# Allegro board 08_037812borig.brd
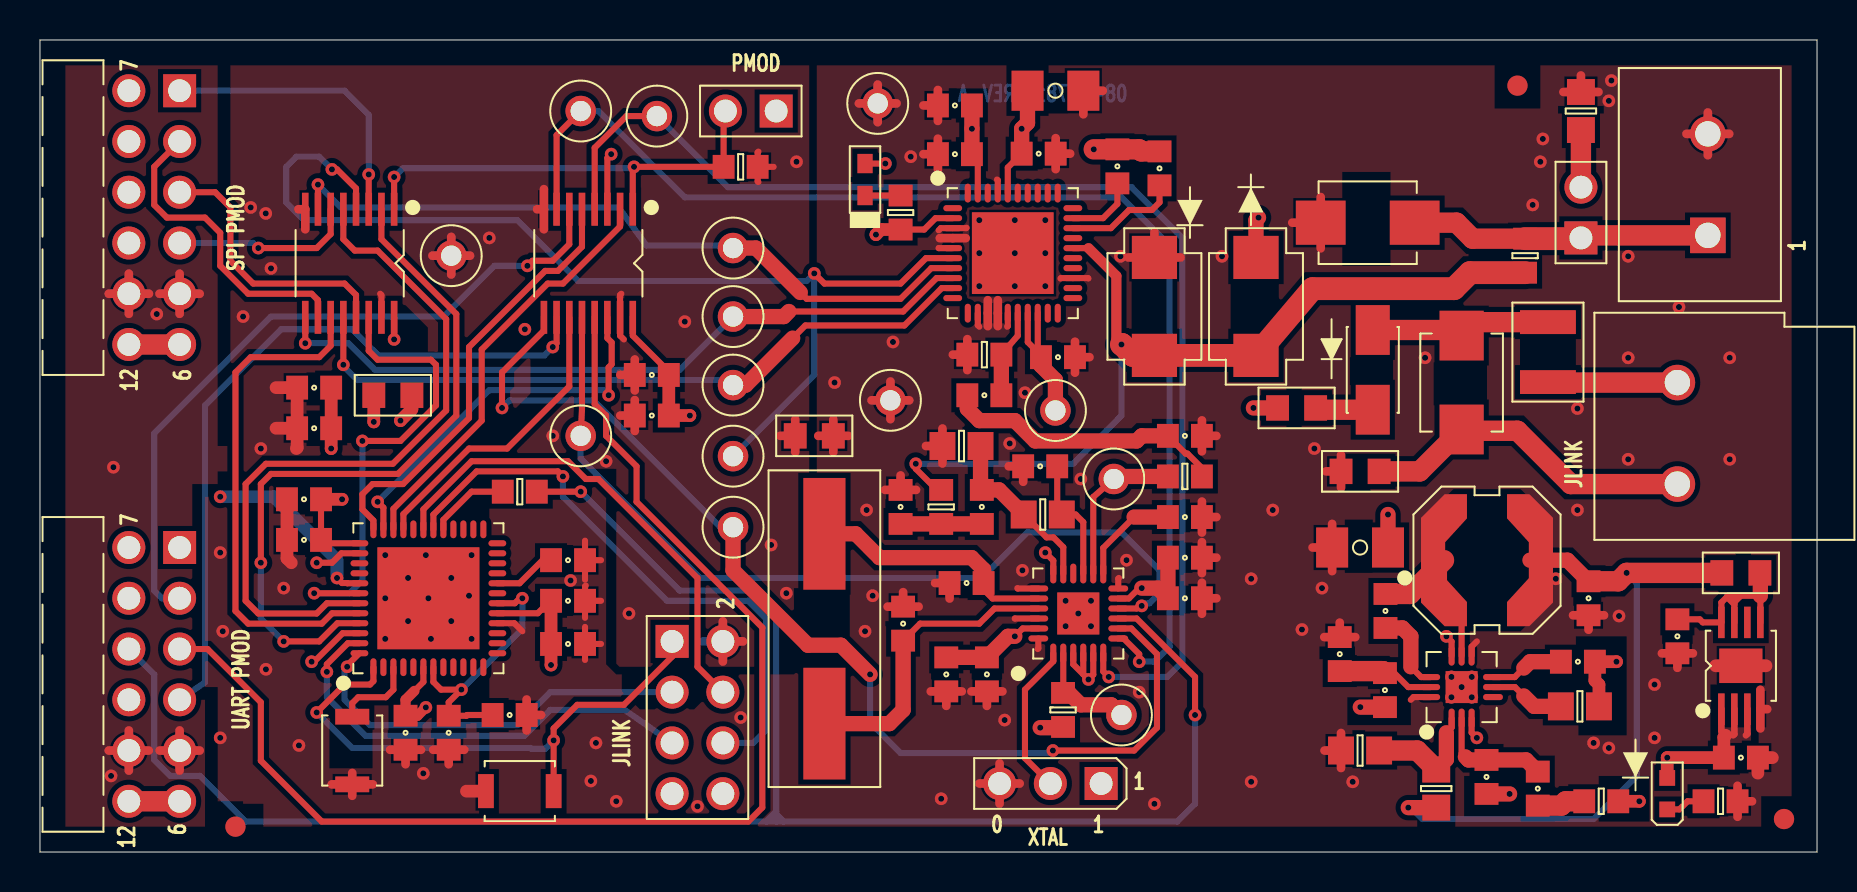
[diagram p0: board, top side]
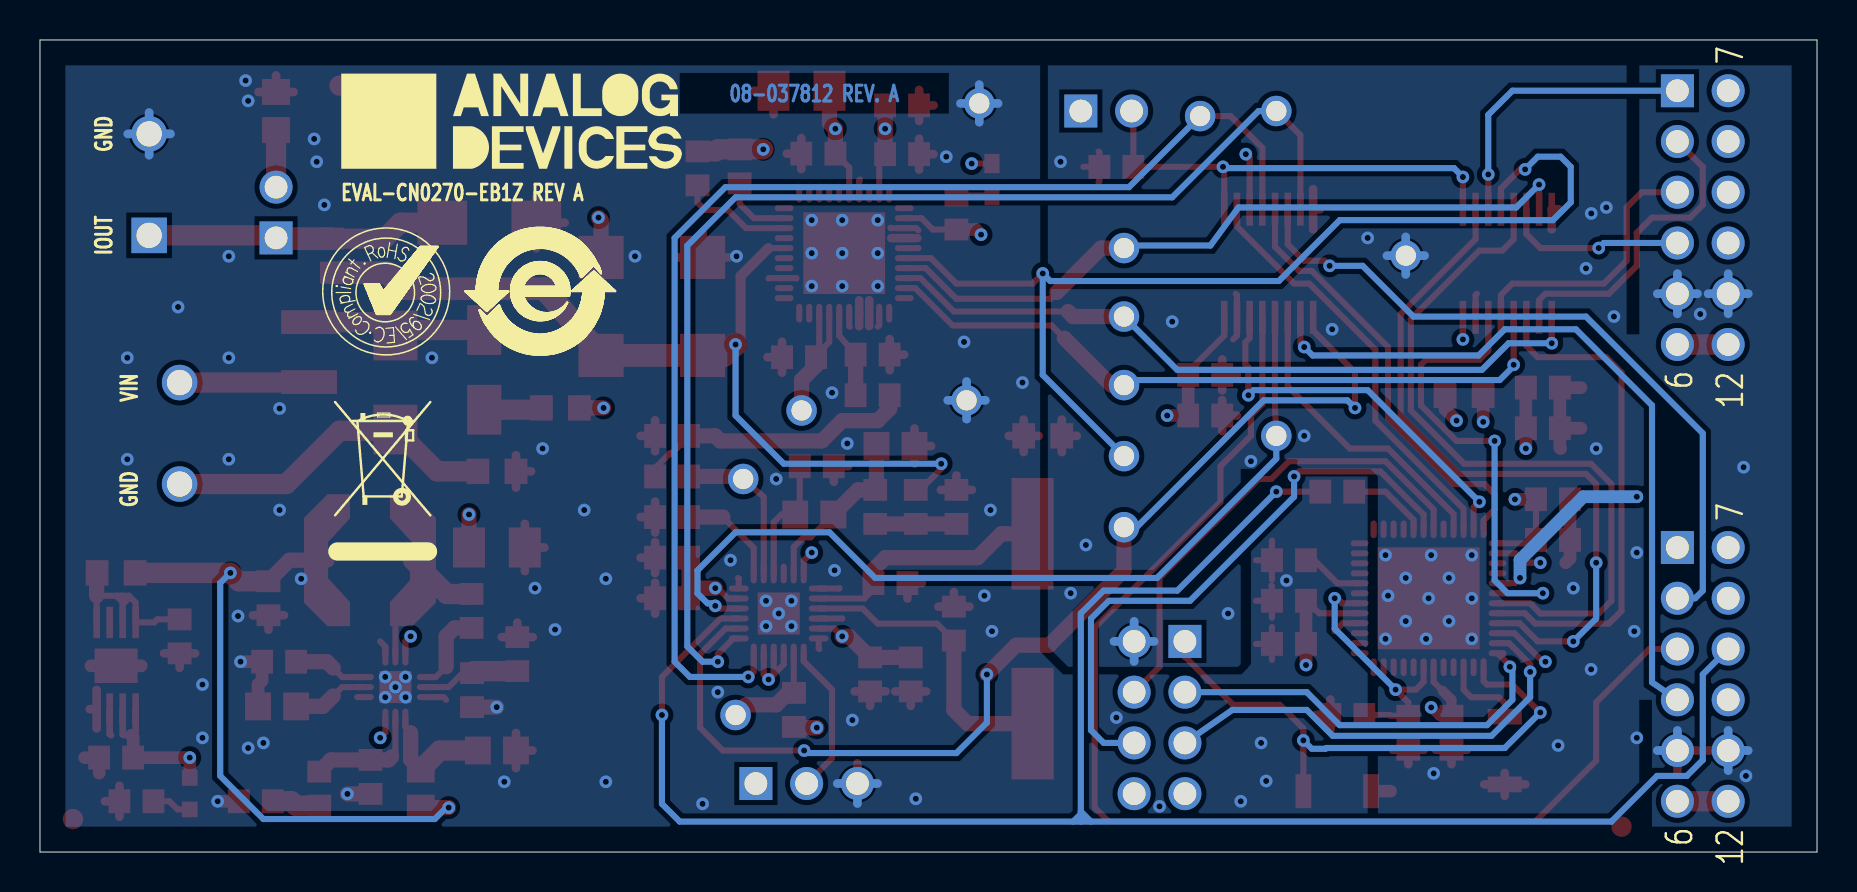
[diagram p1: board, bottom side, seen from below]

Outline 88.9 x 40.64 mm; copper layers: TOP, L2_GND, L3_PWR, BOTTOM. Coordinates in mm from the lower left corner of the outline.
Outline path: 0,40.64 0,0 88.9,0 88.9,40.64 0,40.64

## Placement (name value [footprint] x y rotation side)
C1  4700PF  [C0603]  56.01 34.21 270 top
C2  22NF  [C0603]  53.9 34.32 270 top
C3  36pF  [C0603]  43.18 11.43 90 top
C4  1uF  [C0603]  50.04 19.3 180 top
C5  36pF  [C0603]  46.35 13.46 180 top
C6  1uF  [C0603]  57.28 16.76 0 top
C7  300pF  [C0603]  47.12 17.27 270 top
C8  150PF  [C0603]  43.05 17.27 90 top
C9  0.1uF  [C0603]  57.28 14.73 180 top
C10  10uF  [C0603]  57.28 12.7 0 top
C11  10uF  [C0603]  47.37 8.89 270 top
C12  0.1uF  [C0603]  45.34 8.89 270 top
C13  10uF  [C1206H71]  50.8 38.1 180 top
C14  0.1uF  [C0603]  49.96 34.95 180 top
C15  0.1uF  [C0603]  45.77 37.36 180 top
C16  10uF  [C0603]  45.77 34.93 0 top
C17  0.1uF  [C0603]  50.93 24.77 0 top
C18  1uF  [C1206]  66.04 15.24 180 top
C19  680pF  [C0603]  74.93 3.17 270 top
C20  6.8PF  [C0603]  72.36 3.76 270 top
C21  0.01uF  [C0603]  76.94 9.53 0 top
C22  0.01uF  [C0603]  67.31 12.06 90 top
C23  1uF  [C0603]  67.28 8.1 90 top
C24  1uF  [C0603]  65.02 9.91 90 top
C25  4.7uF  [C0603]  77.47 12.7 270 top
C26  4.7uF  [C0603]  85.09 4.72 0 top
C27  10uF  [C0603]  13.72 23.24 180 top
C28  0.1uF  [C0603]  13.72 21.21 180 top
C29  10uF  [C0603]  30.61 23.88 180 top
C30  0.1uF  [C0603]  30.61 21.84 180 top
C31  1uF  [C0603]  81.91 10.79 270 top
C32  0.47uF  [C0603]  26.42 14.61 180 top
C33  0.47uF  [C0603]  20.45 5.97 90 top
C34  0.47uF  [C0603]  23.49 6.86 180 top
C35  10uF  [C0603]  26.42 12.57 180 top
C36  0.1uF  [C0603]  26.42 10.41 180 top
C37  0.1uF  [C0603]  13.21 17.65 180 top
C38  10uF  [C0603]  13.21 15.62 180 top
C39  0.1uF  [C0603]  18.29 5.97 270 top
CD  5002  [CNKEY5001TP]  30.86 36.83 0 top
CH  8200PF  [C0603]  47.24 22.86 0 top
CL  4700PF  [C0603]  57.28 20.83 0 top
CLKOUT  5002  [CNKEY5001TP]  54.1 6.86 0 top
CR1  SMBJ24CA  [DO214AA-5]  66.42 31.5 180 top
CR2  SMBJ36CA  [DO214AA-5]  71.12 23.5 90 top
D1  SMBJ24A  [DO214AA4]  55.75 27.3 90 top
D2  SMBJ24A  [DO214AA4]  60.83 27.3 270 top
D3  SBR1A40SA-13  [SMA-2]  66.67 24.13 90 top
DS1  APT1608SRCPRV  [LED0603]  41.27 33.66 90 top
DS2  LNJ312G83RA (green)  [LED0603-2]  81.41 2.92 90 top
E1  330OHM  [L0805]  62.86 22.23 180 top
E2  330OHM  [L0805]  66.04 19.05 180 top
E3  330OHM  [L0805]  38.73 20.83 0 top
E4  1K OHM  [L0805]  17.65 22.86 0 top
E5  1K OHM  [L0805]  85.09 13.97 0 top
F1  0.05A  [F1210_A]  75.44 25.02 90 top
HART_O  5002  [CNKEY5001TP]  53.72 18.67 0 top
JP1  TSW-102-08-G-S  [CNSAMTEC1X2H330LD36]  36.83 37.08 180 top
JP2  SAMTECTSW10608GS3PIN  [CNBERG1X3H205LD36]  53.09 3.43 180 top
L1  12uH  [LSMSQ236H138]  72.39 14.61 0 top
LATCH  5002  [CNKEY5001TP]  34.67 19.81 0 top
NOREF  -  []  -27.56 -102.74 0 top
NOREF#2  -  []  -150.37 -245.05 0 top
NOREF#3  -  []  0 0 90 top
NOREF#4  -  [unnamed#2]  87.25 1.65 0 top
NOREF#5  -  []  0 0 0 top
NOREF#6  -  []  87.25 1.65 0 top
NOREF#7  -  [unnamed#2]  73.91 38.35 0 top
NOREF#8  -  []  -150.37 -245.05 0 top
NOREF#9  -  []  0 40.64 270 top
NOREF#10  -  []  -150.37 -245.05 0 top
NOREF#11  -  []  88.9 0 0 top
NOREF#12  -  []  0 0 0 top
NOREF#13  -  []  -48.45 134.05 0 top
NOREF#14  -  [unnamed#2]  9.78 1.27 0 top
NOREF#15  -  []  0 40.64 0 top
NOREF#16  -  []  88.9 40.64 0 top
NOREF#17  -  []  88.9 40.64 180 top
NOREF#18  -  []  87.25 1.65 0 top
NOREF#19  -  []  88.9 0 90 top
NOREF#20  -  []  41.91 69.02 0 top
NOREF#21  -  []  88.9 0 0 top
NOREF#22  -  []  71.75 19.68 180 bottom
NOREF#23  -  []  63.88 28.07 180 bottom
NOREF#24  -  []  71.63 27.94 180 bottom
NOREF#25  -  []  65.28 36.58 180 bottom
P1  TSW-106-25-F-D-RA  [CNHDRRA2X6H240]  6.98 38.1 270 top
P2  TSW-102-08-G-S  [CNSAMTEC1X2H330LD36]  77.09 30.73 90 top
P3  OSTTC022162  [CNHDR1X2H406]  83.44 30.86 90 top
P4  ED125/2DS  [CNOSTED125-2DS]  81.91 23.5 270 top
P5  TSW-106-25-F-D-RA  [CNHDRRA2X6H240]  6.98 15.24 270 top
P7  TSW-104-08-T-D  [CNSAMTEC2X4H330LD36]  31.62 10.54 270 top
R1  10K  [R0603]  35.05 34.29 0 top
R2  1.2MEG  [R0805]  50.16 16.89 180 top
R3  1.2MEG  [R0805]  46.1 20.32 180 top
R4  0  [R0603]  24 18.03 0 top
R5  150K  [R0603]  45.08 17.27 90 top
R6  0  [R0603]  51.18 7.11 270 top
R7  15K  [R0603]  47.24 24.89 180 top
R8  130  [R0603]  43.05 32 270 top
R9  18  [R0603]  74.29 29.84 90 top
R10  499  [R0805]  77.09 37.08 90 top
R11  127K  [R0805]  77.04 7.29 0 top
R12  130  [R0603]  78.1 2.54 0 top
R13  13.7K  [R0805]  66.04 5.08 180 top
R14  73.2K  [R0805]  69.85 3.17 270 top
R15  130  [R0603]  84.07 2.54 0 top
REF  5002  [CNKEY5001TP]  50.8 22.1 0 top
RH  27K  [R0603]  57.28 18.8 0 top
RTS  5002  [CNKEY5001TP]  34.67 16.26 0 top
RXD  5002  [CNKEY5001TP]  27.05 20.83 0 top
S1  B3U-1000P  [SWSML118W98H69]  24 3.05 0 top
S2  B3U-1000P  [SWSML118W98H69]  15.62 5.08 90 top
SCLK  5002  [CNKEY5001TP]  34.67 30.23 0 top
SDI  5002  [CNKEY5001TP]  34.67 26.8 0 top
SDO  5002  [CNKEY5001TP]  34.67 23.37 0 top
TP1  5001  [CNKEY5001TP]  42.54 22.61 0 top
TP2  5001  [CNKEY5001TP]  41.91 37.47 0 top
TP3  5001  [CNKEY5001TP]  20.57 29.84 0 top
TXD  5002  [CNKEY5001TP]  27.05 37.08 0 top
U1  AD5700-1BCPZ  [QFN24_4X4_PAD2_1X2_1]  51.94 11.94 0 top
U2  AD5420ACPZ  [QFN40_6X6_PAD4_1X4_1]  48.67 29.97 270 top
U3  ADP2441ACPZ  [QFN12_3X3_PAD1_6X1_6]  71.12 8.26 0 top
U4  ADP124ARHZ-3.3-R7  [MSOP8_PAD2_16X1_73]  85.09 9.32 0 top
U5  ADUCM360BCPZ128  [QFN48_7X7_PAD5_1X5_1]  19.43 12.7 0 top
U6  ADG774BRQZ  [QSOP16]  15.49 29.46 180 top
U7  ADG774BRQZ  [QSOP16]  27.43 29.46 180 top
Y1  3.6864MEGHz  [YSML450W190H160]  39.24 11.18 90 top

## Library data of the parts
C1 CL = CAP: Tolerance: 10; User Part Number: UPN; alternate symbols: (C0402H22_ALT,C0201-2,C0402_A,C0402_ALT); part number: CAP_SM-4700PF,50V,10,E000427,C0603; tolerance: 10
C2 = CAP: Tolerance: 10; User Part Number: UPN; alternate symbols: (C0402H22_ALT,C0201-2,C0402_A,C0402_ALT); part number: CAP_SM-22NF,16V,10,E000327,C0603; tolerance: 10
C3 C5 = CAP: Tolerance: 5; User Part Number: UPN; alternate symbols: (C0402H22_ALT,C0201-2,C0402_A,C0402_ALT); part number: CAP_SM-36PF,50V,5,E011673,C0603; tolerance: 5
C4 C6 C23 C24 C31 = CAP: Tolerance: 10; User Part Number: UPN; alternate symbols: (C0402H22_ALT,C0201-2,C0402_A,C0402_ALT); part number: CAP_SM-1UF,10V,10,E011783,C0603; tolerance: 10
C7 = CAP: Tolerance: 5; User Part Number: UPN; alternate symbols: (C0402H22_ALT,C0201-2,C0402_A,C0402_ALT); part number: CAP_SM-300PF,50V,5,E012930,C0603; tolerance: 5
C8 = CAP: Tolerance: 5; User Part Number: UPN; alternate symbols: (C0402H22_ALT,C0201-2,C0402_A,C0402_ALT); part number: CAP_SM-150PF,50V,5,E000416,C0603; tolerance: 5
C9 C12 C28 C30 C36 C37 C39 = CAP: Tolerance: 10; User Part Number: UPN; alternate symbols: (C0402H22_ALT,C0201-2,C0402_A,C0402_ALT); part number: CAP_SM-0.1UF,16V,10,E015036,C0603; tolerance: 10
C10 C11 C16 C27 C29 C35 C38 = CAP: Tolerance: 20; User Part Number: UPN; alternate symbols: (C0402H22_ALT,C0201-2,C0402_A,C0402_ALT); part number: CAP_SM-10UF,10V,20,E018646,C0603; tolerance: 20
C13 = CAP: Tolerance: 10; User Part Number: UPN; alternate symbols: (C0402H22_ALT,C0201-2,C0402_A,C0402_ALT); part number: CAP_SM-10UF,50V,10,E013961,C1206H71; tolerance: 10
C14 C15 C17 = CAP: Tolerance: 10; User Part Number: UPN; alternate symbols: (C0402H22_ALT,C0201-2,C0402_A,C0402_ALT); part number: CAP_SM-0.1UF,50V,10,E011865,C0603; tolerance: 10
C18 = CAP: Tolerance: 10; User Part Number: UPN; alternate symbols: (C0402H22_ALT,C0201-2,C0402_A,C0402_ALT); part number: CAP_SM-1UF,50V,10,E011257,C1206; tolerance: 10
C19 = CAP: Tolerance: 5; User Part Number: UPN; alternate symbols: (C0402H22_ALT,C0201-2,C0402_A,C0402_ALT); part number: CAP_SM-680PF,50V,5,E010191,C0603; tolerance: 5
C20 = CAP: Tolerance: 5; User Part Number: UPN; alternate symbols: (C0402H22_ALT,C0201-2,C0402_A,C0402_ALT); part number: CAP_SM-6.8PF,50V,5,E000408,C0603; tolerance: 5
C21 C22 = CAP: Tolerance: 5; User Part Number: UPN; alternate symbols: (C0402H22_ALT,C0201-2,C0402_A,C0402_ALT); part number: CAP_SM-0.01UF,25V,5,E012400,C0603; tolerance: 5
C25 C26 = CAP: Tolerance: 10; User Part Number: UPN; alternate symbols: (C0402H22_ALT,C0201-2,C0402_A,C0402_ALT); part number: CAP_SM-4.7UF,16V,10,E020112,C0603; tolerance: 10
C32-C34 = CAP: Tolerance: 10; User Part Number: UPN; alternate symbols: (C0402H22_ALT,C0201-2,C0402_A,C0402_ALT); part number: CAP_SM-0.47UF,25V,10,E010966,C0603; tolerance: 10
CD CLKOUT HART_O LATCH REF RTS RXD SCLK SDI SDO TXD = CNTP1P: User Part Number: UPN; alternate symbols: (CNBANANA_ALT); part number: CNTP1P_TH-5002,E006153,CNKEY5001TP
CH = CAP: Tolerance: 5; User Part Number: UPN; alternate symbols: (C0402H22_ALT,C0201-2,C0402_A,C0402_ALT); part number: CAP_SM-8200PF,50V,5,E000433,C0603; tolerance: 5
CR1 = DIOZNR_V2: Tolerance: 5; User Part Number: UPN; part number: DIOZNR_V2_SM-SMBJ24CA,24V,5,E019419,DO214AA-5; tolerance: 5
CR2 = DIO_V3: Tolerance: N/A; User Part Number: UPN; part number: DIO_V3_SM-SMBJ36CA,36V,N/A,E019417,DO214AA-5; tolerance: N/A
D1 D2 = DIO: User Part Number: UPN; Tolerance: 5; alternate symbols: (DO15_ALT); part number: DIO_SM-SMBJ24A,24V,5,E019418,DO214AA4; tolerance: 5
D3 = DIO: User Part Number: UPN; Tolerance: N/A; alternate symbols: (DO15_ALT); part number: DIO_SM-SBR1A40SA-13,40V,N/A,E015547,SMA-2; tolerance: N/A
DS1 = DIOLED: Tolerance: N/A; User Part Number: UPN; part number: DIOLED_SM-APT1608SRCPRV,1.85V,N/A,E018073,LED0603; tolerance: N/A
DS2 = DIOLED: Tolerance: N/A; User Part Number: UPN; part number: DIOLED_SM-LNJ312G83RA (GREEN),2.03V,N/A,E014696,LED0603-2; tolerance: N/A
E1-E3 = FERRITE: Tolerance: 25; User Part Number: UPN; part number: FERRITE_SM-330OHM,25,E018120,L0805; tolerance: 25
E4 E5 = FERRITE: Tolerance: N/A; User Part Number: UPN; part number: FERRITE_SM-1K OHM,N/A,E011583,L0805; tolerance: N/A
F1 = FSFUSE: User Part Number: UPN; part number: FSFUSE_SM-0.05A,60V,E017159,BEL FUSE INC,0ZCB0005FF2E,SCD-016141,F1210_A,N/A
JP1 P2 = CN2P: User Part Number: UPN; part number: CN2P_TH-TSW-102-08-G-S,E006296,SAMTEC,TSW-102-08-G-S,SCD-002447,CNSAMTEC1X2H330LD36
JP2 = CN3P: User Part Number: UPN; part number: CN3P_TH-SAMTECTSW10608GS3PIN,E000812,CNBERG1X3H205LD36
L1 = IND: User Part Number: UPN; Tolerance: 20; alternate symbols: (L0402-2,L0603_ALT); part number: IND_SM-12UH,20,E020136,LSMSQ236H138; tolerance: 20
P1 P5 = CN12P_V3: User Part Number: UPN; part number: CN12P_V3_TH-TSW-106-25-F-D-RA,E018495,CNHDRRA2X6H240
P3 = CN2P: User Part Number: UPN; part number: CN2P_TH-OSTTC022162,E016936,ON SHORE TECHNOLOGY INC,OSTTC022162,SCD-016004,CNHDR1X2H406
P4 = CN2P: User Part Number: UPN; part number: CN2P_TH-ED125/2DS,E020249,ON SHORE TECHNOLOGY INC,ED125/2DS,SCD-017963,CNOSTED125-2DS
P7 = CN8P_ODD_EVEN: User Part Number: UPN; part number: CN8P_ODD_EVEN_TH-TSW-104-08-T-D,E006295,CNSAMTEC2X4H330LD36
R1 = RES: Tolerance: 1; User Part Number: UPN; alternate symbols: (RRAD984L1500W75H520LD32;TO220H590_ALT;R0402_A;R0603_A); part number: RES_SM-10K,E003671,1/10W,1,PANASONIC,ERJ-3EKF1002V,SCD-001006,R0603,N/A; tolerance: 1
R2 R3 = RES: Tolerance: 1; User Part Number: UPN; alternate symbols: (RRAD984L1500W75H520LD32;TO220H590_ALT;R0402_A;R0603_A); part number: RES_SM-1.2MEG,E003658,1/8W,1,PANASONIC,ERJ-6ENF1204V,SCD-001006,R0805,N/A; tolerance: 1
R4 R6 = RES: Tolerance: 1; User Part Number: UPN; alternate symbols: (RRAD984L1500W75H520LD32;TO220H590_ALT;R0402_A;R0603_A); part number: RES_SM-0,E004207,1/16W,1,MULTICOMP,MC0603WG00000T5E-TC,SCD-003454,R0603,N/A; tolerance: 1
R5 = RES: Tolerance: 1; User Part Number: UPN; alternate symbols: (RRAD984L1500W75H520LD32;TO220H590_ALT;R0402_A;R0603_A); part number: RES_SM-150K,E003672,1/10W,1,PANASONIC,ERJ-3EKF1503V,SCD-001006,R0603,N/A; tolerance: 1
R7 = RES: Tolerance: 0.1; User Part Number: UPN; alternate symbols: (RRAD984L1500W75H520LD32;TO220H590_ALT;R0402_A;R0603_A); part number: RES_SM-15K,E019547,1/10W,0.1,YAGEO,RT0603BRB0715KL,SCD-002985,R0603,N/A; tolerance: 0.1
R8 R12 R15 = RES: Tolerance: 1; User Part Number: UPN; alternate symbols: (RRAD984L1500W75H520LD32;TO220H590_ALT;R0402_A;R0603_A); part number: RES_SM-130,E003676,1/10W,1,PANASONIC,ERJ-3EKF1300V,SCD-001006,R0603,N/A; tolerance: 1
R9 = RES: Tolerance: 1; User Part Number: UPN; alternate symbols: (RRAD984L1500W75H520LD32;TO220H590_ALT;R0402_A;R0603_A); part number: RES_SM-18,E010183,1/10W,1,PANASONIC,ERJ-3EKF18R0V,SCD-001006,R0603,N/A; tolerance: 1
R10 = RES: Tolerance: 1; User Part Number: UPN; alternate symbols: (RRAD984L1500W75H520LD32;TO220H590_ALT;R0402_A;R0603_A); part number: RES_SM-499,E003414,1/8W,1,PANASONIC,ERJ-6ENF4990V,SCD-001006,R0805,N/A; tolerance: 1
R11 = RES: Tolerance: 1; User Part Number: UPN; alternate symbols: (RRAD984L1500W75H520LD32;TO220H590_ALT;R0402_A;R0603_A); part number: RES_SM-127K,E007901,1/8W,1,PANASONIC,ERJ-6ENF1273V,SCD-001006,R0805,N/A; tolerance: 1
R13 = RES: Tolerance: 1; User Part Number: UPN; alternate symbols: (RRAD984L1500W75H520LD32;TO220H590_ALT;R0402_A;R0603_A); part number: RES_SM-13.7K,E003644,1/8W,1,PANASONIC,ERJ-6ENF1372V,SCD-001006,R0805,N/A; tolerance: 1
R14 = RES: Tolerance: 1; User Part Number: UPN; alternate symbols: (RRAD984L1500W75H520LD32;TO220H590_ALT;R0402_A;R0603_A); part number: RES_SM-73.2K,E015003,1/8W,1,PANASONIC,ERJ-6ENF7322V,SCD-001006,R0805,N/A; tolerance: 1
RH = RES: Tolerance: 1; User Part Number: UPN; alternate symbols: (RRAD984L1500W75H520LD32;TO220H590_ALT;R0402_A;R0603_A); part number: RES_SM-27K,E004226,1/16W,1,MULTICOMP,MC 0.063W 0603 1% 27K.,SCD-003454,R0603,N/A; tolerance: 1
S1 S2 = SWSPST2PIN_V2: User Part Number: UPN; part number: SWSPST2PIN_V2_SM-B3U-1000P,E016303,SWSML118W98H69
TP1-TP3 = CNTP1P: User Part Number: UPN; alternate symbols: (CNBANANA_ALT); part number: CNTP1P_TH-5001,E005347,CNKEY5001TP
U1 = AD5700: User Part Number: UPN; part number: AD5700_SM-AD5700-1BCPZ,E019439,QFN24_4X4_PAD2_1X2_1,N/A
U2 = AD54X0: User Part Number: UPN; part number: AD54X0_SM-AD5420ACPZ,E012259,QFN40_6X6_PAD4_1X4_1,N/A
U3 = ADP2441: User Part Number: UPN; part number: ADP2441_SM-ADP2441ACPZ,E017338,QFN12_3X3_PAD1_6X1_6,N/A
U4 = ADP124: User Part Number: UPN; part number: ADP124_SM-ADP124ARHZ-3.3-R7,E012626,MSOP8_PAD2_16X1_73,N/A
U5 = ADUCM36X: User Part Number: UPN; part number: ADUCM36X_SM-ADUCM360BCPZ128,E018148,QFN48_7X7_PAD5_1X5_1,N/A
U6 U7 = ADG774: User Part Number: UPN; part number: ADG774_SM-ADG774BRQZ,E020256,ADI,ADG774BRQZ,HTTP://WWMFG.ANALOG.COM/WWMFG/APPS/HLM/LSF/EDIT/7667/ASSIGNMENTID/148940,QSOP16,N/A
Y1 = XTAL: User Part Number: UPN; part number: XTAL_SM-3.6864MEGHZ,E013571,YSML450W190H160

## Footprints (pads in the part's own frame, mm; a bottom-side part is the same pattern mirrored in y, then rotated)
C0603
  rect 1.092x1.194 smd: 1(-0.851,0) 2(0.851,0)
C1206
  rect 1.6x2.007 smd: 1(-1.397,0) 2(1.397,0)
C1206H71
  rect 1.6x2.007 smd: 1(-1.397,0) 2(1.397,0)
CNBERG1X3H205LD36
  rect 1.651x1.651 hole 1.143: 1(0,0)
  round 1.651 hole 1.143: 2(2.54,0) 3(5.08,0)
CNHDR1X2H406
  rect 1.778x1.778 hole 1.27: 1(0,0)
  round 1.778 hole 1.27: 2(5.08,0)
CNHDRRA2X6H240
  rect 1.651x1.651 hole 1.143: 1(0,0)
  round 1.651 hole 1.143: 2(2.54,0) 3(5.08,0) 4(7.62,0) 5(10.16,0) 6(12.7,0) 7(0,-2.54) 8(2.54,-2.54) 9(5.08,-2.54) 10(7.62,-2.54) 11(10.16,-2.54) 12(12.7,-2.54)
CNKEY5001TP
  round 1.524 hole 1.016: 1(0,0)
CNOSTED125-2DS
  round 1.778 hole 1.27: 1(0,0) 2(5.08,0)
CNSAMTEC1X2H330LD36
  rect 1.651x1.651 hole 1.143: 1(0,0)
  round 1.651 hole 1.143: 2(2.54,0)
CNSAMTEC2X4H330LD36
  rect 1.651x1.651 hole 1.143: 1(0,0)
  round 1.651 hole 1.143: 2(0,2.54) 3(2.54,0) 4(2.54,2.54) 5(5.08,0) 6(5.08,2.54) 7(7.62,0) 8(7.62,2.54)
DO214AA4
  rect 2.159x2.261 smd: A(2.451,0) C(-2.451,0)
DO214AA-5
  rect 2.489x2.21 smd: 1(-2.35,0) 2(2.35,0)
F1210_A
  rect 1.194x2.794 smd: 1(-1.5,0) 2(1.5,0)
L0805
  rect 1.143x1.27 smd: 1(-0.953,0) 2(0.953,0)
LED0603
  rect 0.965x0.762 smd: A(0.8,0) C(-0.8,0)
LED0603-2
  rect 0.787x0.787 smd: A(0.787,0) C(-0.787,0)
LSMSQ236H138
  custom 0.575x0.575 smd: 1(-2.151,0) 2(2.151,0)
MSOP8_PAD2_16X1_73
  rect 0.33x1.575 smd: 1(-0.975,-2.171) 2(-0.325,-2.171) 3(0.325,-2.171) 4(0.975,-2.171) 5(0.975,2.171) 6(0.325,2.171) 7(-0.325,2.171) 8(-0.975,2.171)
  rect 2.159x1.727 smd: PAD(0,0)
QFN12_3X3_PAD1_6X1_6
  oval 0.305x0.991 smd: 1(-0.5,-1.57) 2(0,-1.57) 3(0.5,-1.57) 7(0.5,1.57) 8(0,1.57) 9(-0.5,1.57)
  oval 0.991x0.305 smd: 4(1.57,-0.5) 5(1.57,0) 6(1.57,0.5) 10(-1.57,0.5) 11(-1.57,0) 12(-1.57,-0.5)
  rect 1.6x1.6 smd: PAD(0,0)
QFN24_4X4_PAD2_1X2_1
  oval 0.305x0.991 smd: 1(-1.25,-2) 2(-0.75,-2) 3(-0.25,-2) 4(0.25,-2) 5(0.75,-2) 6(1.25,-2) 13(1.25,2) 14(0.75,2) 15(0.25,2) 16(-0.25,2) 17(-0.75,2) 18(-1.25,2)
  oval 0.991x0.305 smd: 7(2,-1.25) 8(2,-0.75) 9(2,-0.25) 10(2,0.25) 11(2,0.75) 12(2,1.25) 19(-2,1.25) 20(-2,0.75) 21(-2,0.25) 22(-2,-0.25) 23(-2,-0.75) 24(-2,-1.25)
  rect 2.108x2.108 smd: PAD(0,0)
QFN40_6X6_PAD4_1X4_1
  oval 0.305x0.94 smd: 1(-2.25,-3.005) 2(-1.75,-3.005) 3(-1.25,-3.005) 4(-0.75,-3.005) 5(-0.25,-3.005) 6(0.25,-3.005) 7(0.75,-3.005) 8(1.25,-3.005) 9(1.75,-3.005) 10(2.25,-3.005) 21(2.25,3.005) 22(1.75,3.005) 23(1.25,3.005) 24(0.75,3.005) 25(0.25,3.005) 26(-0.25,3.005) 27(-0.75,3.005) 28(-1.25,3.005) 29(-1.75,3.005) 30(-2.25,3.005)
  oval 0.94x0.305 smd: 11(3.005,-2.25) 12(3.005,-1.75) 13(3.005,-1.25) 14(3.005,-0.75) 15(3.005,-0.25) 16(3.005,0.25) 17(3.005,0.75) 18(3.005,1.25) 19(3.005,1.75) 20(3.005,2.25) 31(-3.005,2.25) 32(-3.005,1.75) 33(-3.005,1.25) 34(-3.005,0.75) 35(-3.005,0.25) 36(-3.005,-0.25) 37(-3.005,-0.75) 38(-3.005,-1.25) 39(-3.005,-1.75) 40(-3.005,-2.25)
  rect 4.089x4.089 smd: PAD(0,0)
QFN48_7X7_PAD5_1X5_1
  oval 0.305x0.889 smd: 1(-2.75,-3.45) 2(-2.25,-3.45) 3(-1.75,-3.45) 4(-1.25,-3.45) 5(-0.75,-3.45) 6(-0.25,-3.45) 7(0.25,-3.45) 8(0.75,-3.45) 9(1.25,-3.45) 10(1.75,-3.45) 11(2.25,-3.45) 12(2.75,-3.45) 25(2.75,3.45) 26(2.25,3.45) 27(1.75,3.45) 28(1.25,3.45) 29(0.75,3.45) 30(0.25,3.45) 31(-0.25,3.45) 32(-0.75,3.45) 33(-1.25,3.45) 34(-1.75,3.45) 35(-2.25,3.45) 36(-2.75,3.45)
  oval 0.889x0.305 smd: 13(3.45,-2.75) 14(3.45,-2.25) 15(3.45,-1.75) 16(3.45,-1.25) 17(3.45,-0.75) 18(3.45,-0.25) 19(3.45,0.25) 20(3.45,0.75) 21(3.45,1.25) 22(3.45,1.75) 23(3.45,2.25) 24(3.45,2.75) 37(-3.45,2.75) 38(-3.45,2.25) 39(-3.45,1.75) 40(-3.45,1.25) 41(-3.45,0.75) 42(-3.45,0.25) 43(-3.45,-0.25) 44(-3.45,-0.75) 45(-3.45,-1.25) 46(-3.45,-1.75) 47(-3.45,-2.25) 48(-3.45,-2.75)
  rect 5.105x5.105 smd: PAD(0,0)
QSOP16
  rect 0.33x1.651 smd: 1(-2.223,-2.705) 2(-1.587,-2.705) 3(-0.953,-2.705) 4(-0.318,-2.705) 5(0.318,-2.705) 6(0.953,-2.705) 7(1.587,-2.705) 8(2.223,-2.705) 9(2.223,2.705) 10(1.587,2.705) 11(0.953,2.705) 12(0.318,2.705) 13(-0.318,2.705) 14(-0.953,2.705) 15(-1.587,2.705) 16(-2.223,2.705)
R0603
  rect 1.092x1.194 smd: 1(-0.851,0) 2(0.851,0)
R0805
  rect 1.295x1.397 smd: 1(-0.953,0) 2(0.953,0)
SMA-2
  rect 2.489x1.702 smd: A(1.995,0) C(-1.995,0)
SWSML118W98H69
  rect 0.787x1.702 smd: 1(-1.694,0) 2(1.694,0)
unnamed#2
  round 1.016 smd: (0,0)
YSML450W190H160
  rect 5.588x2.108 smd: 1(-4.75,0) 2(4.75,0)

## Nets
+3.3V: C9.2(N2) C10.1(N1) C11.1(N1) C12.1(N1) C15.1(N1) C16.2(N2) C26.1(N1) C37.1(N1) C38.1(N1) C39.1(N1) DS1.A(P) DS2.A(P) E4.2(N2) JP1.1(N1) JP2.1(N1) P7.8(N8) U1.3(CLK_CFG0) U1.4(CLK_CFG1) U1.5(RESET_N) U1.11(IOVCC) U1.18(VCC) U1.23(REF_EN) U2.39(DVCC) U4.1(VOUT1) U4.2(VOUT2) U4.3(VOUT_SENSE) U5.6(IOVDD1) U5.37(IOVDD2)
AGND: C3.2(N2) C4.2(N2) C5.2(N2) C6.2(N2) C8.2(N2) C9.1(N1) C10.2(N2) C11.2(N2) C12.2(N2) C13.1(N1) C14.1(N1) C15.2(N2) C16.1(N1) C17.2(N2) C18.2(N2) C20.2(N2) C21.2(N2) C23.1(N1) C24.2(N2) C25.2(N2) C26.2(N2) C31.2(N2) C32.1(N1) C34.1(N1) C35.1(N1) C36.1(N1) CL.2(N2) CR1.2(N2) D1.A(P) E2.2(N2) E3.2(N2) JP2.3(N3) P3.2(N2) R3.2(N2) R7.2(N2) R10.2(N2) R11.2(N2) R12.2(N2) R13.2(N2) R15.2(N2) TP1.1(N1) TP2.1(N1) U1.12(DGND1) U1.19(AGND) U1.22(DGND2) U1.24(FILTER_SEL) U1.PAD(EP) U2.3(GND1) U2.4(GND2) U2.5(CLEAR) U2.12(GND6) U2.13(GND7) U2.14(GND3) U2.15(GND4) U2.23(DVCC_SELECT) U2.37(GND5) U2.PAD U3.7(PGND) U3.12(AGND) U3.PAD U4.4(GND) U4.PAD(EP) U5.16(AGND)
AVDD: C1.1(N1) C2.1(N1) C13.2(N2) C14.2(N2) C18.1(N1) D2.C(N) E1.2(N2) U2.36(AVDD) U3.3(EN) U3.9(VIN)
AVDD_ADUC: C35.2(N2) C36.2(N2) E4.1(N1) U5.17(AVDD)
DGND: C27.2(N2) C28.2(N2) C29.2(N2) C30.2(N2) C33.1(N1) C37.2(N2) C38.2(N2) C39.2(N2) E3.1(N1) P1.5(GND1) P1.11(GND2) P5.5(GND1) P5.11(GND2) P7.2(N2) R1.2(N2) S1.1(A) S2.1(A) TP3.1(N1) U5.PAD U6.8(GND) U6.15(EN_N) U7.8(GND) U7.15(EN_N)
ADUC_CD: U5.34(P0.5/CTS/IRQ1) U7.2(S1A)
ADUC_LATCH: U5.45(P1.7/IRQ7/PWM5/CS0_N) U6.2(S1A)
ADUC_RTS: U5.33(P0.4/RTS/ECLKO) U7.11(S3A)
ADUC_RXD: U5.35(P0.6/IRQ2/SIN) U7.14(S4A)
ADUC_SCLK: U5.43(P1.5/IRQ5/PWM3/SCLK0) U6.5(S2A)
ADUC_SDI: U5.44(P1.6/IRQ6/PWM4/MOSI0) U6.11(S3A)
ADUC_SDO: U5.42(P1.4/PWM2/MISO0) U6.14(S4A)
ADUC_TXD: U5.36(P0.7/POR/SOUT) U7.5(S2A)
DACREF: C17.1(N1) REF.1(N1) U2.17(REFOUT) U2.18(REFIN)
DUPLEX: P5.9(P9) R4.2(N2) U1.9(DUPLEX)
FAULT: P1.9(P9) R8.2(N2) U2.2(FAULT_N) U5.41(P1.3/PWM1/DSR)
HART_CD: CD.1(N1) U1.6(CD) U7.4(D1)
HART_CLK: P5.10(P10) R6.2(N2) U5.38(P1.0/IRQ3/PWMSYNC/EXTCLK) U5.46(P2.0/SCL/UARTCLK)
HART_RTS: RTS.1(N1) U1.8(RTS_N) U7.9(D3)
HART_RXD: RXD.1(N1) U1.10(RXD) U7.12(D4)
HART_TXD: TXD.1(N1) U1.7(TXD) U7.7(D2)
IOVDD_ADUC: C27.1(N1) C28.1(N1) C29.1(N1) C30.1(N1) U6.16(VDD) U7.16(VDD)
LATCH: LATCH.1(N1) U2.6(LATCH) U6.4(D1)
PMOD_CD: P5.1(P1) U7.3(S1B)
PMOD_LATCH: P1.1(P1) U6.3(S1B)
PMOD_RTS: P5.4(P4) U7.10(S3B)
PMOD_RXD: P5.3(P3) U7.13(S4B)
PMOD_SCLK: P1.4(P4) U6.6(S2B)
PMOD_SDI: P1.2(P2) U6.10(S3B)
PMOD_SDO: P1.3(P3) U6.13(S4B)
PMOD_TXD: P5.2(P2) U7.6(S2B)
RESET: P7.1(N1) S1.2(B) U5.1(RESET_N)
RXD: P7.6(N6) U5.30(P0.1/SCLK1/SCL/SIN)
SCLK: SCLK.1(N1) U2.7(SCLK) U6.7(D2)
SDI: SDI.1(N1) U2.8(SDIN) U6.9(D3)
SDO: SDO.1(N1) U2.9(SDO) U6.12(D4)
SWCLK: P7.5(N5) U5.47(SWCLK)
SWDIO: P7.3(N3) U5.48(SWDIO)
TXD: P7.4(N4) U5.31(P0.2/MOSI1/SDA/SOUT)
UNNAMED_3_AD54X0_I52_CAP1: C1.2(N2) U2.28(CAP1)
UNNAMED_3_AD54X0_I52_CAP2: C2.2(N2) U2.29(CAP2)
UNNAMED_3_AD54X0_I52_IOUT: D1.C(N) D2.A(P) R5.2(N2) R9.1(N1) U2.26(IOUT)
UNNAMED_3_AD54X0_I52_RSET: CH.2(N2) R7.1(N1) U2.16(RSET)
UNNAMED_3_AD5700_I2_ADCIP: C7.1(N1) R2.2(N2) R3.1(N1) U1.17(ADC_IP)
UNNAMED_3_AD5700_I2_CLKOUT: CLKOUT.1(N1) R6.1(N1) U1.2(CLKOUT)
UNNAMED_3_AD5700_I2_HARTOUT: HART_O.1(N1) RH.1(N1) U1.14(HART_OUT)
UNNAMED_3_AD5700_I2_REF: C4.1(N1) R2.1(N1) U1.15(REF)
UNNAMED_3_AD5700_I2_REGCAP: C6.1(N1) U1.13(REG_CAP)
UNNAMED_3_AD5700_I2_XTAL1: C3.1(N1) U1.21(XTAL1) Y1.1(N1)
UNNAMED_3_AD5700_I2_XTAL2: C5.1(N1) U1.20(XTAL2) Y1.2(N2)
UNNAMED_3_AD5700_I2_XTALENN: JP2.2(N2) U1.1(XTAL_EN_N)
UNNAMED_3_ADG774_I113_IN: JP1.2(N2) R1.1(N1) U6.1(IN) U7.1(IN)
UNNAMED_3_CAP_I25_N2: C7.2(N2) C8.1(N1) R5.1(N1)
UNNAMED_3_CAP_I30_N1: CH.1(N1) CL.1(N1) RH.2(N2)
UNNAMED_3_CN2P_I50_N1: CR1.1(N1) P2.1(N1) P3.1(N1) R9.2(N2)
UNNAMED_3_CN2P_I77_N2: P2.2(N2) R10.1(N1)
UNNAMED_3_DIOLED_I83_N: DS1.C(N) R8.1(N1)
UNNAMED_4_ADP124_I110_EN: C31.1(N1) E5.2(N2) U4.5(EN) U4.7(VIN1) U4.8(VIN2)
UNNAMED_4_ADP2441_I109_BST: C22.1(N1) U3.10(BST)
UNNAMED_4_ADP2441_I109_COMP: C19.1(N1) C20.1(N1) U3.2(COMP)
UNNAMED_4_ADP2441_I109_FB: R13.1(N1) R14.1(N1) U3.1(FB)
UNNAMED_4_ADP2441_I109_FREQ: R11.1(N1) U3.5(FREQ)
UNNAMED_4_ADP2441_I109_SS: C21.1(N1) U3.6(SS/TRK)
UNNAMED_4_ADP2441_I109_SW: C22.2(N2) L1.1(N1) U3.8(SW)
UNNAMED_4_ADP2441_I109_VCC: C23.2(N2) C24.1(N1) U3.11(VCC)
UNNAMED_4_CAP_I116_N1: C25.1(N1) E5.1(N1) L1.2(N2) R14.2(N2)
UNNAMED_4_CAP_I120_N2: C19.2(N2) R12.1(N1)
UNNAMED_4_CN2P_I112_N1: F1.1(N1) P4.1(N1)
UNNAMED_4_CN2P_I112_N2: CR2.1(N1) E2.1(N1) P4.2(N2)
UNNAMED_4_DIO_I99_N: D3.C(N) E1.1(N1)
UNNAMED_4_DIO_I99_P: CR2.2(N2) D3.A(P) F1.2(N2)
UNNAMED_4_DIOLED_I134_N: DS2.C(N) R15.1(N1)
UNNAMED_8_ADUCM36X_I1_AVDDREG: C33.2(N2) C34.2(N2) U5.7(DVDD_REG) U5.18(AVDD_REG)
UNNAMED_8_ADUCM36X_I1_INTREF: C32.2(N2) U5.20(INT_REF)
UNNAMED_8_ADUCM36X_I1_P0: R4.1(N1) U5.29(P0.0/MISO1)
UNNAMED_8_ADUCM36X_I1_P2: S2.2(B) U5.3(P2.2/BM)
UNNAMED_8_CN12PV3_I78_VCC1: P1.6(VCC1) P1.12(VCC2)
UNNAMED_8_CN12PV3_I81_VCC1: P5.6(VCC1) P5.12(VCC2)

Pads without a net: P1 7 8 10; P5 7 8; P7 7; U1 16; U2 1 10 11 19 20 21 22 24 25 27 30 31 32 33 34 35 38 40; U3 4; U4 6; U5 2 4 5 8 9 10 11 12 13 14 15 19 21 22 23 24 25 26 27 28 32 39 40

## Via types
v1: diameter 0.635, hole 0.305, TOP to BOTTOM, 175 vias

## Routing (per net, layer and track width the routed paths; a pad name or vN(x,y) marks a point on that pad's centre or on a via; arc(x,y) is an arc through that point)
+3.3V: length 49.6
  TOP w0.305: DS1.A v1(42.29,34.46) ; U5.6 19.18,8.51 18.73,8.06 ; 52.19,8.89 51.69,9.39 U1.3 ; 52.19,8.89 v1(52.45,8.64) 52.69,8.88 U1.5 ; 52.19,8.89 U1.4 ; v1(48.77,10.79) 49.16,11.19 U1.23 ; v1(50.29,14.99) 50.69,14.58 U1.18 ; C37.1 C38.1 14.23,15.45 U5.37 ; v1(55.12,13.21) 54.99,13.21 54.47,12.69 U1.11 ; U2.39 46.92,34.63 C16.2
  TOP w0.33: 84.33,5.84 84.11,6.06 U4.1 ; U4.3 85.42,5.91 85.34,5.84 ; 84.71,5.84 84.76,5.9 U4.2
  TOP w0.508: v1(19.3,7.24) 18.88,6.82 C39.1 18.29,7.62 18.73,8.06
  TOP w0.635: DS2.A v1(81.41,4.72) C26.1 84.24,5.75 84.33,5.84 ; v1(18.03,21.59) 18.61,22.16 E4.2 ; C37.1 v1(15.11,17.65)
  TOP w0.762: v1(55.12,13.21) 55.92,13.21 C10.1 C9.2 ; v1(48.77,10.79) 48.43,10.79 C11.1 C12.1 ; C16.2 v1(46.62,36.2) C15.1
  L3_PWR w0.432: JP1.1 37.83,37.08 ; JP1.1 36.83,38.09 ; JP1.1 35.83,37.08 ; JP1.1 36.83,36.08 ; JP2.1 54.09,3.43 ; JP2.1 53.09,4.43 ; JP2.1 53.09,2.43 ; 35.17,2.92 P7.8 34.16,3.92
AGND: length 153.9
  TOP w0.305: 47.88,33.66 47.92,33.62 U2.37 ; 52.45,28.7 52.43,28.72 U2.23 51.07,28.72 51.05,28.7 ; 27.27,11.26 C36.1 ; C36.1 27.27,9.61 ; C36.1 28.07,10.41 ; 71.88,10.54 71.62,10.28 U3.7 ; C32.1 28.07,14.61 ; C32.1 27.27,15.58 ; C32.1 27.27,13.63 ; 44.96,30.23 44.96,30.22 U2.5 ; U1.12 53.94,13.68 53.97,13.72 ; C35.1 28.07,12.57 ; C35.1 27.27,13.3 27.3,13.33 ; C35.1 27.27,11.72 ; 44.96,31.11 45.06,31.22 U2.3 46.33,31.22 46.35,31.24 ; 24.13,11.05 23.73,11.45 U5.16 ; U2.15 48.42,26.32 48.39,26.29 ; 46.99,26.29 46.92,26.36 U2.12 ; U1.22 48.77,11.69 48.77,11.68 ; 68.58,7.62 68.71,7.75 U3.12 ; U1.19 48.92,13.19 48.89,13.21 ; U1.24 49.94,10.19 49.91,10.16
  TOP w0.432: 24.35,6.08 C34.1 ; C34.1 25.07,6.86 ; C34.1 24.35,7.63 ; C25.2 78.25,11.85 ; C25.2 77.47,11.12 ; C25.2 76.69,11.85 ; 58.13,13.96 C9.1 ; C9.1 58.13,15.51 ; C9.1 58.85,14.73 ; C6.2 58.85,16.76 ; C6.2 58.13,15.99 ; C6.2 58.13,17.54 ; 58.13,11.92 C10.2 ; C10.2 58.85,12.7 ; C10.2 58.13,13.48 ; TP2.1 41.91,38.41 ; TP2.1 40.97,37.47 ; TP2.1 41.91,36.52 ; TP2.1 42.85,37.47 ; P3.2 83.44,37.01 ; P3.2 83.44,34.87 ; P3.2 84.51,35.94 ; P3.2 82.37,35.94 ; C18.2 64.64,16.42 ; C18.2 64.64,14.06 ; C18.2 63.66,15.24 ; C8.2 43.83,18.12 ; C8.2 43.05,18.85 ; C8.2 42.28,18.12 ; 64.34,19.05 E2.2 ; E2.2 65.09,19.86 ; E2.2 65.09,18.24 ; 48.01,3.43 48.01,4.43 ; 48.01,3.43 49.01,3.43 ; 48.01,3.43 48.01,2.43 ; 48.01,3.43 47,3.43 ; 46.31,30.72 U2.4 45.01,30.72 ; 39.69,20.01 E3.2 ; E3.2 39.69,21.64 ; E3.2 38.94,20.83 ; E3.2 40.44,20.83 ; C31.2 82.69,9.94 ; C31.2 81.14,9.94 ; C31.2 81.91,9.22 ; R7.2 46.39,25.67 ; R7.2 45.67,24.89 ; R7.2 46.39,24.12 ; 47.42,26.32 U2.13 47.42,27.62 ; C24.2 65.8,10.76 ; C24.2 64.25,10.76 ; C24.2 65.02,11.48 ; 47.37,7.31 C11.2 ; C11.2 46.6,8.04 ; C11.2 48.15,8.04 ; 44.2,37.36 C15.2 ; C15.2 44.92,38.14 ; C15.2 44.92,36.59 ; C12.2 46.11,8.04 ; C12.2 45.34,7.31 ; C12.2 44.56,8.04 ; CL.2 58.85,20.83 ; CL.2 58.13,20.05 ; CL.2 58.13,21.6 ; 64.07,30.21 CR1.2 ; CR1.2 62.65,31.5 ; CR1.2 64.07,32.78 ; R15.2 84.92,3.32 ; R15.2 84.92,1.76 ; R15.2 85.65,2.54 ; 47.92,27.62 U2.14 47.92,26.32 ; D1.A 57.06,29.76 ; D1.A 54.44,29.76 ; D1.A 55.75,31.01 ; 76.21,38.04 R10.2 ; R10.2 77.09,38.86 ; R10.2 77.97,38.04 ; 44.78,13.46 C5.2 45.5,12.69 ; C17.2 51.78,25.54 ; C17.2 52.5,24.77 ; C17.2 51.78,23.99 ; C16.1 44.92,35.7 ; C16.1 44.2,34.93 ; C16.1 44.92,34.15 ; 50.81,34.18 C14.1 ; C14.1 51.54,34.95 ; C14.1 50.81,35.73 ; C3.2 43.18,13.01 ; C3.2 42.4,12.28 ; C3.2 43.96,12.28 ; 64.26,5.08 R13.2 ; R13.2 65.09,4.2 ; R13.2 65.09,5.96 ; 49.19,18.53 C4.2 48.46,19.3 ; 86.07,6.19 U4.4 ; U4.4 86.07,8.12 ; U4.4 86.41,7.15 ; R3.2 45.15,21.2 ; R3.2 45.15,19.44 ; R3.2 44.32,20.32 ; TP1.1 42.54,23.55 ; TP1.1 41.6,22.61 ; TP1.1 42.54,21.67 ; TP1.1 43.49,22.61 ; 53.18,38.1 C13.1 52.2,36.92
  TOP w0.635: 83.83,9.32 U4.PAD 86.35,9.32 ; 86.67,4.72 C26.2 85.94,3.95 ; R11.2 77.99,8.38 77.79,8.59 C21.2 v1(78.87,9.53) ; R12.2 v1(80.01,2.54)
  TOP w0.762: v1(66.05,7.25) C23.1 ; C20.2 v1(73.52,2.91)
  L2_GND w0.432: 48.01,2.43 48.01,3.43 ; 48.01,3.43 47,3.43 ; 48.01,3.43 49.01,3.43 ; 48.01,3.43 48.01,4.43 ; 42.54,21.67 TP1.1 ; TP1.1 42.54,23.55 ; TP1.1 43.49,22.61 ; TP1.1 41.6,22.61 ; TP2.1 42.85,37.47 ; TP2.1 41.91,36.52 ; TP2.1 41.91,38.41 ; TP2.1 40.97,37.47 ; P3.2 83.44,37.01 ; P3.2 82.37,35.94 ; P3.2 84.51,35.94 ; P3.2 83.44,34.87
  BOTTOM w0.432: 48.01,3.43 49.01,3.43 ; 48.01,3.43 48.01,2.43 ; 48.01,3.43 47,3.43 ; 40.97,37.47 TP2.1 ; TP2.1 41.91,38.41 ; TP2.1 42.85,37.47 ; TP2.1 41.91,36.52 ; 42.54,21.67 TP1.1 ; TP1.1 43.49,22.61 ; TP1.1 42.54,23.55 ; TP1.1 41.6,22.61 ; P3.2 83.44,37.01 ; P3.2 84.51,35.94 ; P3.2 82.37,35.94 ; P3.2 83.44,34.87
  vias: v1(26.54,13.59) v1(27.56,3.56) v1(27.81,5.46) v1(28.83,2.54) v1(32.89,2.29) v1(35.05,6.73) v1(39.75,23.5) v1(41.27,11.05) v1(41.35,17.12) v1(41.66,12.83) v1(42.67,25.53) v1(43.56,34.8) v1(45.08,2.67) v1(46.99,31.62) v1(46.99,29.97) v1(46.99,28.32) v1(48.26,6.6) v1(48.51,20.45) v1(48.77,31.62) v1(48.77,29.97) v1(48.77,28.32) v1(49.15,14.1) v1(49.28,22.99) v1(50.29,31.62) v1(50.29,29.97) v1(50.29,28.32) v1(51.31,12.57) v1(51.31,11.3) v1(51.94,11.94) v1(52.07,18.67) v1(52.58,12.57) v1(52.58,11.3) v1(54.05,29.82) v1(54.36,14.61) v1(54.99,8) v1(55.75,2.41) v1(59.13,29.82) v1(60.59,13.67) v1(60.59,3.51) v1(61.67,17.12) v1(63.13,11.13) v1(63.75,20.19) v1(64.13,13.21) v1(65.67,3.51) v1(69.29,24.74) v1(70.61,8.76) v1(70.61,7.75) v1(71.12,8.26) v1(71.63,8.76) v1(71.63,7.75) v1(74.68,32.39) v1(75.06,34.54) v1(75.18,35.69) v1(75.83,13.67) v1(76.91,22.2) v1(76.91,17.12) v1(77.72,5.46) v1(78.49,37.59) v1(78.49,5.21) v1(78.61,38.61) v1(78.99,11.81) v1(79.45,29.82) v1(79.45,24.74) v1(79.45,19.66) v1(80.77,8.38) v1(80.77,5.71) v1(81.99,27.28) v1(84.53,24.74) v1(84.53,19.66)
AVDD: length 15.9
  TOP w0.305: v1(71.88,5.71) 71.62,5.98 U3.3 ; C14.2 48.42,34.26 U2.36 ; U3.9 70.62,10.53 v1(70.36,10.79)
  TOP w0.762: v1(60.71,22.23) E1.2 ; C13.2 49.4,36.49 v1(49.11,36.2) C14.2 ; v1(60.96,31.75) 60.83,31.62 D2.C ; C18.1 v1(67.44,16.89)
  TOP w1.016: C1.1 55.09,35.06 54.99,35.17 C2.1 v1(52.72,35.17)
AVDD_ADUC: length 7.5
  TOP w0.305: U5.17 24.9,11.95 25.53,12.57 C35.2
  TOP w0.635: C35.2 C36.2 v1(25.57,9.36) ; E4.1 v1(16.7,21.53)
DGND: length 101.7
  TOP w0.305: R1.2 36.7,34.29 ; R1.2 35.9,35.01 35.94,35.05 ; R1.2 35.9,33.57 35.94,33.53 ; 29.08,27.94 29.02,27.88 U7.15 29.02,25.84 29.21,25.65 ; U6.15 17.08,27.88 17.02,27.94
  TOP w0.432: 4.44,5.08 5.45,5.08 ; 4.44,5.08 3.44,5.08 ; 4.44,5.08 4.44,6.08 ; 4.44,5.08 4.44,4.08 ; C39.2 19.06,5.12 ; C39.2 17.51,5.12 ; C39.2 18.29,4.39 ; 34.16,9.54 P7.2 ; P7.2 34.16,11.54 ; P7.2 35.17,10.54 ; P1.5 7.99,27.94 ; P1.5 6.98,28.94 ; P1.5 6.98,26.94 ; P1.5 5.98,27.94 ; TP3.1 21.51,29.84 ; TP3.1 19.63,29.84 ; TP3.1 20.57,28.9 ; TP3.1 20.57,30.79 ; 37.78,20.01 E3.1 ; E3.1 37.03,20.83 ; E3.1 37.78,21.64 ; 12.93,32.17 U6.8 13.27,31.17 ; 6.98,5.08 7.99,5.08 ; 6.98,5.08 6.98,6.08 ; 6.98,5.08 5.98,5.08 ; 6.98,5.08 6.98,4.08 ; C29.2 29.76,24.65 ; C29.2 29.76,23.1 ; C29.2 29.03,23.88 ; 15.62,2.81 S2.1 ; S2.1 14.59,3.39 ; S2.1 16.65,3.39 ; S2.1 15.62,3.96 ; 25.21,31.17 U7.8 ; U7.8 24.87,32.17 ; U7.8 25.21,33.17 ; C30.2 29.76,22.62 ; C30.2 29.03,21.84 ; C30.2 29.76,21.07 ; 19.67,5.12 C33.1 ; C33.1 21.22,5.12 ; C33.1 20.45,4.39 ; 3.44,27.94 P1.11 ; P1.11 4.44,26.94 ; P1.11 4.44,28.94 ; P1.11 5.45,27.94
  TOP w0.635: C28.2 11.81,21.21 ; C28.2 12.87,20.23 12.83,20.19 ; C28.2 C27.2 11.81,23.24 ; 12.57,14.48 12.36,14.69 C38.2 C37.2 ; S1.1 21.34,3.05
  L2_GND w0.305: 18.03,3.17 17.68,3.53
  L2_GND w0.432: 34.16,9.54 P7.2 ; P7.2 33.16,10.54 ; P7.2 34.16,11.54 ; P7.2 35.17,10.54 ; 4.44,5.08 4.44,6.08 ; 4.44,5.08 5.45,5.08 ; 4.44,5.08 4.44,4.08 ; 4.44,5.08 3.44,5.08 ; 5.98,27.94 P1.5 ; P1.5 6.98,26.94 ; P1.5 6.98,28.94 ; P1.5 7.99,27.94 ; 5.98,5.08 6.98,5.08 ; 6.98,5.08 6.98,6.08 ; 6.98,5.08 6.98,4.08 ; 6.98,5.08 7.99,5.08 ; 4.44,26.94 P1.11 ; P1.11 5.45,27.94 ; P1.11 3.44,27.94 ; P1.11 4.44,28.94 ; TP3.1 21.51,29.84 ; TP3.1 20.57,30.79 ; TP3.1 19.63,29.84 ; TP3.1 20.57,28.9
  BOTTOM w0.432: 20.57,28.9 TP3.1 ; TP3.1 19.63,29.84 ; TP3.1 21.51,29.84 ; TP3.1 20.57,30.79 ; P1.11 4.44,28.94 ; P1.11 5.45,27.94 ; P1.11 3.44,27.94 ; P1.11 4.44,26.94 ; 5.98,27.94 P1.5 ; P1.5 6.98,26.94 ; P1.5 7.99,27.94 ; P1.5 6.98,28.94 ; 4.44,5.08 4.44,6.08 ; 4.44,5.08 4.44,4.08 ; 4.44,5.08 3.44,5.08 ; 33.16,10.54 P7.2 ; P7.2 35.17,10.54 ; P7.2 34.16,11.54 ; P7.2 34.16,9.54 ; 7.99,5.08 6.98,5.08 6.98,6.08
  vias: v1(3.56,3.81) v1(3.67,19.26) v1(5.84,26.92) v1(9.02,14.99) v1(9.02,5.71) v1(9.14,11.05) v1(10.16,26.8) v1(10.54,32.26) v1(11.05,20.19) v1(11.29,31.96) v1(11.3,9.14) v1(11.56,29.21) v1(12.19,13.21) v1(12.95,5.33) v1(17.27,14.86) v1(17.27,12.7) v1(17.27,10.67) v1(18.41,13.72) v1(18.41,11.56) v1(19.18,3.94) v1(19.3,14.86) v1(19.43,12.7) v1(19.56,10.67) v1(20.57,13.72) v1(20.57,11.56) v1(21.46,12.83) v1(21.59,14.86) v1(21.59,10.67) v1(22.48,30.73) v1(24.26,26.16) v1(25.65,20.83) v1(28.32,19.56) v1(29.46,11.94) v1(32.26,26.54) v1(36.58,15.37) v1(37.34,12.95) v1(37.85,34.54)
ADUC_CD: length 21.2
  TOP w0.305: U5.34 17.68,17.17 22.1,21.59 22.1,25.15 25.4,28.45 26.16,28.45 29.02,31.31 U7.2
ADUC_LATCH: length 35.6
  TOP w0.305: U5.45 14.88,11.45 13.97,10.54 v1(12.19,10.54) ; v1(11.05,14.48) 11.05,18.41 11.56,18.92 17.91,18.92 20.83,21.84 20.83,26.92 17.08,30.67 U6.2
  BOTTOM w0.305: v1(11.05,14.48) 11.05,11.68 v1(12.19,10.54)
ADUC_RTS: length 15.2
  TOP w0.305: U7.11 26.48,23.3 23.37,20.19 21.46,20.19 18.18,16.91 U5.33
ADUC_RXD: length 19.5
  TOP w0.305: U7.14 28.38,25.72 28.6,25.5 28.6,24.41 28.45,24.26 v1(28.45,22.86) ; v1(16.89,17.53) 17.18,17.24 U5.35
  BOTTOM w0.305: v1(16.89,17.53) 22.48,23.11 28.19,23.11 v1(28.45,22.86)
ADUC_SCLK: length 36.4
  TOP w0.305: U6.5 15.18,30.67 15.75,30.1 16.89,30.1 20.32,26.67 20.32,22.1 17.65,19.43 11.3,19.43 10.29,18.41 10.29,12.57 10.92,11.94 13.84,11.94 14.36,12.45 U5.43
ADUC_SDI: length 25.4
  TOP w0.305: U5.44 14.62,11.95 14.1,11.43 10.41,11.43 9.78,12.06 9.78,24 10.54,24.77 13.97,24.77 14.54,25.34 U6.11
ADUC_SDO: length 23.7
  TOP w0.305: U5.42 13.72,12.95 v1(13.72,12.95) ; v1(16.13,20.57) 18.03,20.57 19.81,22.35 19.81,24.38 19.56,24.64 16.89,24.64 16.45,25.08 U6.14
  BOTTOM w0.305: v1(13.72,12.95) 15.48,12.95 16.13,13.6 v1(16.13,20.57)
ADUC_TXD: length 22.1
  TOP w0.305: U5.36 16.68,16.59 16.13,17.14 16.13,17.91 16.64,18.41 18.16,18.41 21.46,21.72 21.46,25.27 25.27,29.08 25.91,29.08 27.11,30.29 U7.5
DACREF: length 7.4
  TOP w0.305: U2.17 49.42,25.52 49.92,25.02 ; 49.92,25.02 50.08,24.86 C17.1 ; 49.92,25.02 U2.18
  TOP w0.762: REF.1 50.8,23.62 50.08,24.35 C17.1
DUPLEX: length 97.4
  TOP w0.305: v1(27.05,18.03) R4.2 ; v1(57.78,6.86) 57.78,8.76 54.86,11.69 U1.9
  BOTTOM w0.305: 36.83,1.91 36.83,2.03 ; 36.83,1.91 37.21,1.52 ; 36.83,1.91 36.83,1.52 ; 36.83,2.03 36.83,11.94 35.69,13.08 32,13.08 v1(27.05,18.03) ; 36.83,2.03 36.32,1.52 ; 36.32,1.52 10.29,1.52 8,3.81 6.51,3.81 5.71,4.61 5.71,8.89 P5.9 ; 36.32,1.52 36.83,1.52 ; 37.21,1.52 36.83,1.52 ; 37.21,1.52 56.9,1.52 57.78,2.41 v1(57.78,6.86)
FAULT: length 17.5
  TOP w0.305: v1(14.86,13.72) 15.11,13.46 15.37,13.46 15.38,13.45 U5.41 ; U2.2 44.8,31.72 44.23,31.15 R8.2
  TOP w0.635: v1(41.82,30.9) 42.08,31.15 R8.2
  L3_PWR w0.432: 4.44,32.02 P1.9 ; P1.9 5.45,33.02 ; P1.9 3.44,33.02 ; P1.9 4.44,34.02
  BOTTOM w0.635: v1(14.86,13.72) 14.86,14.61 11.69,17.78 v1(9.02,17.78)
HART_CD: length 62.2
  TOP w0.305: U7.4 27.75,35.24 29.34,36.83 CD.1 ; U1.6 53.19,9.04 v1(53.47,8.76)
  BOTTOM w0.305: v1(53.47,8.76) 56.39,8.76 57.15,9.53 57.15,30.73 54.61,33.27 34.42,33.27 CD.1
HART_CLK: length 9.5
  TOP w0.305: U5.46 15.14,10.95 13.72,9.53 v1(13.59,9.53) ; U5.38 15.08,14.95 14.6,14.48 v1(13.84,14.48)
  TOP w0.762: v1(50.04,6.22) 51.14,6.22 R6.2
  L3_PWR w0.432: 4.44,6.62 P5.10 ; P5.10 5.45,7.62 ; P5.10 3.44,7.62
HART_RTS: length 55
  TOP w0.305: v1(50.67,5.08) 54.74,5.08 55.88,6.22 55.88,9.91 54.6,11.19 U1.8 ; U7.9 25.21,26.1 23.11,24 v1(23.11,22.23)
  TOP w0.762: RTS.1 34.67,14.1 38.42,10.35 40.07,10.35 v1(41.53,8.89)
  BOTTOM w0.305: RTS.1 34.04,16.26 27.69,22.61 23.49,22.61 v1(23.11,22.23) ; v1(41.53,8.89) 41.53,6.48 43.05,4.95 50.55,4.95 v1(50.67,5.08)
HART_RXD: length 43.8
  TOP w0.305: RXD.1 27.11,22.16 U7.12 ; U1.10 54.86,12.19 54.99,12.32 v1(55.12,12.32)
  BOTTOM w0.305: RXD.1 27.05,19.68 33.02,13.72 47.12,13.72 49.4,16 54.1,16 56.01,14.1 56.01,12.95 55.5,12.45 55.24,12.45 v1(55.12,12.32)
HART_TXD: length 61.3
  TOP w0.305: TXD.1 25.84,35.88 U7.7 ; U1.7 54.21,10.69 54.99,9.91 v1(54.99,9.53)
  BOTTOM w0.305: v1(54.99,9.53) 55.75,9.53 56.51,10.29 56.51,30.35 54.1,32.77 32.26,32.77 27.94,37.08 TXD.1
IOVDD_ADUC: length 10.9
  TOP w0.305: C29.1 31.46,24.04 29.65,25.84 U7.16 ; v1(17.72,25.65) U6.16
  TOP w0.635: C27.1 C28.1 v1(14.57,20.19) ; v1(32.51,21.84) C30.1 C29.1
LATCH: length 53.9
  TOP w0.305: v1(14.6,34.16) 14.86,34.16 15.81,33.21 U6.4 ; U2.6 44.33,29.72 43.05,28.45 39.24,28.45 v1(38.73,28.96)
  BOTTOM w0.305: LATCH.1 38.73,23.88 v1(38.73,28.96) 38.35,28.57 26.92,28.57 23.88,31.62 13.21,31.62 12.32,32.51 12.32,34.29 12.83,34.8 13.97,34.8 v1(14.6,34.16)
PMOD_CD: length 6.9
  TOP w0.305: U7.3 28.38,34.73 v1(28.57,34.93)
  L3_PWR w0.432: 5.98,15.24 P5.1 ; P5.1 7.99,15.24 ; P5.1 6.98,14.24 ; P5.1 6.98,16.24
PMOD_LATCH: length 14.7
  TOP w0.305: U6.3 v1(16.45,33.91)
  BOTTOM w0.305: v1(16.45,33.91) 16.45,36.89 15.24,38.1 P1.1
PMOD_RTS: length 36.7
  TOP w0.305: v1(25.65,25.27) 25.84,25.46 U7.10
  BOTTOM w0.305: v1(25.65,25.27) 25.23,24.85 16.93,24.85 15.62,26.16 12.06,26.16 8.25,22.35 8.25,8.49 P5.4
PMOD_RXD: length 62.7
  TOP w0.305: P5.3 8.38,10.16 11.05,7.49 11.05,4.57 14.1,1.52 35.43,1.52 36.14,2.23 36.14,11.23 29.84,17.53 29.84,19.3 28.32,20.83 28.32,21.84 27.75,22.42 U7.13
PMOD_SCLK: length 9.2
  TOP w0.305: U6.6 14.54,30.92 13.84,30.23 v1(10.92,30.23)
  BOTTOM w0.305: v1(10.92,30.23) 10.67,30.48 P1.4
PMOD_SDI: length 15.7
  TOP w0.305: P1.2 5.71,34.29 5.71,32.39 6.35,31.75 8.25,31.75 9.02,30.99 9.02,29.34 10.41,27.94 13.59,27.94 13.91,27.62 U6.10
PMOD_SDO: length 13.6
  TOP w0.305: P1.3 8.76,33.02 9.52,32.26 9.52,29.59 10.67,28.45 15.24,28.45 15.81,27.88 U6.13
PMOD_TXD: length 35.7
  TOP w0.305: U7.6 26.48,30.42 25.65,29.59 24.64,29.59 v1(24.38,29.34)
  BOTTOM w0.305: v1(24.38,29.34) 22.73,29.34 20.19,26.8 11.56,26.8 5.71,20.95 5.71,13.08 6.1,12.7 P5.2
RESET: length 28.3
  TOP w0.305: S1.2 v1(25.7,5.59) 25.7,6.18 26.88,7.37 29.21,7.37 31.62,9.78 P7.1 ; U5.1 16.68,8.55 16.51,8.38 15.24,8.38 v1(13.84,6.98)
  BOTTOM w0.305: v1(13.84,6.98) 15.62,5.21 24.55,5.21 24.59,5.17 25.27,5.17 v1(25.7,5.59)
RXD: length 29.9
  TOP w0.305: v1(26.16,18.8) 25.91,19.05 21.84,19.05 19.68,16.89 U5.30
  BOTTOM w0.305: P7.6 35.69,5.46 36.32,6.1 36.32,11.68 35.43,12.57 31.37,12.57 26.16,17.78 v1(26.16,18.8)
SCLK: length 36.2
  TOP w0.305: U6.7 v1(13.91,33.4) ; U2.7 44.59,29.22 43.05,27.69 38.35,27.69 38.04,28
  TOP w0.762: SCLK.1 35.81,30.23 38.04,28
  BOTTOM w0.305: SCLK.1 34.54,30.35 30.34,30.35 28.95,32.26 15.05,32.26 v1(13.91,33.4)
SDI: length 36.1
  TOP w0.305: U6.9 v1(13.27,25.46) ; U2.8 44.85,28.72 43.18,27.05 37.46,27.05
  TOP w0.762: SDI.1 37.21,26.8 37.46,27.05
  BOTTOM w0.305: SDI.1 32,24.13 16.76,24.13 15.43,25.46 v1(13.27,25.46)
SDO: length 35.3
  TOP w0.305: U2.9 45.11,28.22 43.24,26.35 38.29,26.35 37.66,25.72 ; U6.12 v1(15.18,24.38)
  TOP w0.762: SDO.1 35.31,23.37 37.66,25.72
  BOTTOM w0.305: SDO.1 34.42,23.62 15.88,23.62 15.18,24.32 v1(15.18,24.38)
SWCLK: length 22.8
  TOP w0.305: U5.47 15.4,10.45 14.35,9.4 v1(14.35,9.02)
  BOTTOM w0.305: v1(14.35,9.02) 14.35,7.75 16.28,5.82 24.23,5.82 25.53,7.11 29.25,7.11 P7.5
SWDIO: length 20.2
  TOP w0.305: v1(15.37,9.27) 15.37,9.34 U5.48
  BOTTOM w0.305: P7.3 25.53,8 23.88,6.35 16.51,6.35 15.24,7.62 15.24,9.14 v1(15.37,9.27)
TXD: length 24.4
  TOP w0.305: P7.4 32.89,9.27 32.89,13.72 27.94,18.67 27.3,18.67 26.42,19.56 21.59,19.56 19.18,17.15 U5.31
UNNAMED_3_AD54X0_I52_CAP1: length 5.7
  TOP w0.305: U2.28 53.57,31.22 54.48,32.13 55.63,32.13 56.01,32.51 C1.2
UNNAMED_3_AD54X0_I52_CAP2: length 3.6
  TOP w0.305: C2.2 53.9,32.44 53.19,31.72 U2.29
UNNAMED_3_AD54X0_I52_IOUT: length 45.4
  TOP w0.305: R5.2 44.87,18.12 43.81,19.18 v1(43.81,19.43) ; 52.46,30.22 U2.26
  TOP w0.508: 52.46,30.22 53.85,28.83 53.85,25.65 v1(54.1,25.4)
  TOP w1.143: R9.1 71.54,28.99 70.74,28.19 63.67,28.19 D2.A D1.C 54.67,24.85 54.13,25.4 v1(54.1,25.4)
  BOTTOM w0.305: v1(43.81,19.43) 51.69,19.43 54.1,21.84 v1(54.1,25.4)
UNNAMED_3_AD54X0_I52_RSET: length 4.4
  TOP w0.305: U2.16 48.92,25.84 R7.1
  TOP w0.762: CH.2 R7.1
UNNAMED_3_AD5700_I2_ADCIP: length 8.8
  TOP w0.305: R2.2 50.36,15.75 50.7,15.75 51.19,15.26 U1.17
  TOP w0.762: R3.1 47.05,18.19 C7.1 47.98,18.12 R2.2
UNNAMED_3_AD5700_I2_CLKOUT: length 5.4
  TOP w0.305: U1.2 51.19,7.97 R6.1
  TOP w0.762: CLKOUT.1 53.59,7.37 52.07,7.37 51.47,7.96 R6.1
UNNAMED_3_AD5700_I2_HARTOUT: length 8
  TOP w0.305: U1.14 52.69,17.77 HART_O.1
  TOP w0.762: RH.1 53.85,18.8 HART_O.1
UNNAMED_3_AD5700_I2_REF: length 6.3
  TOP w0.305: U1.15 52.19,16.51 51.81,16.89 R2.1 50.89,17.12 C4.1
UNNAMED_3_AD5700_I2_REGCAP: length 5.2
  TOP w0.305: 54.74,16.76 53.19,15.22 U1.13
  TOP w0.762: C6.1 54.74,16.76
UNNAMED_3_AD5700_I2_XTAL1: length 15.1
  TOP w0.305: U1.21 47.75,12.19 46.99,11.43 44.03,11.43 C3.1
  TOP w0.762: C3.1 43.18,7.11 42.49,6.43 Y1.1
UNNAMED_3_AD5700_I2_XTAL2: length 12.6
  TOP w0.305: U1.20 47.65,12.69 47.21,13.13 C5.1
  TOP w0.762: C5.1 47.21,14.14 46.61,14.73 42,14.73 40.81,15.93 Y1.2
UNNAMED_3_AD5700_I2_XTALENN: length 7.6
  TOP w0.305: U1.1 50.69,9.55 49.28,8.13 49.28,4.7 50.55,3.43
UNNAMED_3_ADG774_I113_IN: length 23.3
  TOP w0.305: U6.1 v1(17.72,33.78) ; U7.1 29.65,34.23 v1(29.72,34.29) R1.1 34.2,37 34.29,37.08
  BOTTOM w0.305: v1(29.72,34.29) 29.65,34.23 18.16,34.23 v1(17.72,33.78)
UNNAMED_3_CAP_I25_N2: length 4.1
  TOP w0.762: C8.1 R5.1 C7.2
UNNAMED_3_CAP_I30_N1: length 14.3
  TOP w0.305: RH.2 58.13,19.22 57.4,19.94 57.32,19.94 CL.1
  TOP w0.762: CL.1 55.12,20.83 54.86,20.57 49.78,20.57 48.77,21.59 46.99,21.59 46.39,22.19 CH.1
UNNAMED_3_CN2P_I50_N1: length 15.1
  TOP w1.016: P2.1 77.22,30.86 P3.1 ; CR1.1 70.87,31.5 71.67,30.7 R9.2
  TOP w1.143: R9.2 77.05,30.7 P2.1
UNNAMED_3_CN2P_I77_N2: length 2.9
  TOP w1.016: R10.1 77.09,33.27
UNNAMED_3_DIOLED_I83_N: length 1.8
  TOP w0.305: R8.1 DS1.C
UNNAMED_4_ADP124_I110_EN: length 10.2
  TOP w0.305: 85.09,12.83 86.07,12.83 U4.5 ; 85.09,12.83 84.76,12.5 ; 85.09,12.83 84.84,12.83 ; 84.76,12.5 84.76,12.39 ; 84.76,12.5 84.76,12.76 84.84,12.83 ; 84.84,12.83 84.45,12.83 84.39,12.76 ; 84.76,12.39 U4.7 ; 84.76,12.39 84.39,12.76 ; 84.39,12.76 84.11,12.49 U4.8 83.19,11.49 83.03,11.65 C31.1
  TOP w0.762: E5.2 86.07,13.95 86.07,12.83
UNNAMED_4_ADP2441_I109_BST: length 4.2
  TOP w0.305: U3.10 69.1,8.76 68.58,9.27
  TOP w0.762: C22.1 68.16,11.21 68.58,10.79 68.58,9.27
UNNAMED_4_ADP2441_I109_COMP: length 5.9
  TOP w0.305: U3.2 71.12,4.95 71.31,4.76
  TOP w0.762: C19.1 74.35,4.61 C20.1 71.46,4.61 71.31,4.76
UNNAMED_4_ADP2441_I109_FB: length 6.1
  TOP w0.305: U3.1 70.62,6.23 70.36,5.97
  TOP w0.762: R14.1 70.36,4.64 70.36,5.97
  TOP w1.016: R13.1 68.9,5.08 R14.1
UNNAMED_4_ADP2441_I109_FREQ: length 3.8
  TOP w0.305: U3.5 73.79,8.26 74.23,7.81
  TOP w0.762: 74.23,7.81 74.75,7.29 R11.1
UNNAMED_4_ADP2441_I109_SS: length 3.7
  TOP w0.305: U3.6 73.78,8.76 74.23,9.21
  TOP w0.762: C21.1 74.55,9.53 74.23,9.21
UNNAMED_4_ADP2441_I109_SW: length 8.8
  TOP w0.305: U3.8 71.12,12.06 70.24,12.95 L1.1
  TOP w1.016: C22.2 68.55,12.92 L1.1
UNNAMED_4_ADP2441_I109_VCC: length 4.9
  TOP w0.305: C23.2 67.75,8.95 68.45,8.26 U3.11
  TOP w1.016: C23.2 67.18,9.06 C24.1
UNNAMED_4_CAP_I116_N1: length 34.5
  TOP w0.762: L1.2 76.42,14.61 C25.1 ; R14.2 v1(68.45,2.22)
  TOP w1.016: E5.1 v1(79.38,13.97) 78.96,13.55 C25.1
  BOTTOM w0.305: v1(79.38,13.97) 79.88,13.46 79.88,3.81 77.72,1.65 69.15,1.65 68.58,2.22 v1(68.45,2.22)
UNNAMED_4_CAP_I120_N2: length 2.4
  TOP w1.016: C19.2 76.11,2.32 76.33,2.54 R12.1
UNNAMED_4_CN2P_I112_N1: length 6.5
  TOP w1.016: F1.1 75.8,23.5 P4.1
UNNAMED_4_CN2P_I112_N2: length 16.9
  TOP w1.016: P4.2 76.58,18.41 73.91,21.08 71.18,21.08 CR2.1 69.03,19.05 E2.1
UNNAMED_4_DIO_I99_N: length 2.9
  TOP w1.016: D3.C 63.91,22.14 E1.1
UNNAMED_4_DIO_I99_P: length 9.2
  TOP w1.016: D3.A 70.84,26.12 CR2.2 71.79,26.52 F1.2
UNNAMED_4_DIOLED_I134_N: length 2
  TOP w0.305: R15.1 82.42,2.54 82.02,2.13 DS2.C
UNNAMED_8_ADUCM36X_I1_AVDDREG: length 13.3
  TOP w0.305: v1(24.13,12.7) 24,12.7 23.75,12.45 U5.18 ; U5.7 19.68,8.51 20.07,8.13 v1(21.08,8.13) 20.45,7.49 C33.2 21.34,6.82 21.37,6.86 C34.2
  BOTTOM w0.305: v1(21.08,8.13) 24.13,11.18 v1(24.13,12.7)
UNNAMED_8_ADUCM36X_I1_INTREF: length 3.2
  TOP w0.305: C32.2 25.15,14.61 23.99,13.45 U5.20
UNNAMED_8_ADUCM36X_I1_P0: length 4
  TOP w0.305: U5.29 20.18,16.63 21.59,18.03 R4.1
UNNAMED_8_ADUCM36X_I1_P2: length 4.1
  TOP w0.305: S2.2 15.62,7.45 15.92,7.75 17.3,7.75 17.68,8.13 U5.3
UNNAMED_8_CN12PV3_I78_VCC1: length 2.5
  TOP w1.016: P1.12 P1.6
UNNAMED_8_CN12PV3_I81_VCC1: length 2.5
  TOP w1.016: 4.44,2.54 6.98,2.54

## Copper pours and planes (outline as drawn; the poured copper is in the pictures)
+3.3V on TOP: 83.95,8 83.95,5.46 85.6,5.46 85.6,8
+3.3V on L3_PWR: 87.38,8 87.38,1.78 86.87,1.27 52.2,1.27 52.2,7.37 52.07,7.49 39.37,7.49 35.81,3.94 35.81,2.79 35.56,2.54 33.53,2.54 33.53,3.94 33.27,4.19 15.37,4.19 15.11,4.45 15.11,15.49 14.86,15.75 13.72,15.75 13.46,16 13.46,18.03 15.62,18.03 16.76,16.89 16.76,14.73 16.89,14.61 18.8,14.61 18.92,14.48 18.92,8.26 19.3,7.87 26.42,7.87 26.54,8 26.54,17.27 26.29,17.53 24.26,17.53 24,17.78 24,19.3 23.49,19.81 18.41,19.81 17.65,20.57 17.65,22.35 18.03,22.73 29.59,22.73 31.24,21.08 36.19,21.08 36.45,21.34 36.45,29.59 36.96,30.1 43.81,30.1 43.81,32.26 42.16,33.91 30.48,33.91 29.84,34.54 29.84,39.37 47.24,39.37 47.62,38.99 47.62,31.88 57.78,31.88 59.56,30.1 59.56,4.7 74.93,4.7 74.93,8
AGND on TOP: 22.48,1.27 22.48,18.8 28.32,18.8 28.32,9.4 28.83,8.89 37.72,8.89 38.86,10.03 38.86,10.54 39.24,10.54 39.24,10.16 40.51,10.16 40.51,13.84 39.24,13.84 39.24,13.08 38.86,13.08 38.86,39.37 72.77,39.37 72.77,37.21 75.06,37.21 75.06,39.37 85.72,39.37 85.73,39.37 87.63,39.37 87.63,39.37 87.63,2.79 86.11,2.79 86.11,1.27 23.49,1.27 ; 55 cut-outs
AGND on BOTTOM: 22.48,1.27 22.48,18.8 28.32,18.8 28.32,9.4 28.83,8.89 37.72,8.89 38.86,10.03 38.86,39.37 87.63,39.37 87.63,1.27 23.49,1.27 ; 4 cut-outs
AGND on L2_GND: 38.86,39.37 87.63,39.37 87.63,1.27 23.49,1.27 22.48,1.27 22.48,18.8 28.32,18.8 28.32,9.4 28.83,8.89 37.72,8.89 38.86,10.03 ; 3 cut-outs
AVDD on L3_PWR: 59.82,30.23 57.91,32.13 48.01,32.13 46.86,33.27 46.86,39.37 59.56,39.37 59.56,39.37 87.63,39.37 87.63,8.51 74.55,8.51 74.55,5.21 60.07,5.21 59.82,5.46
AVDD_ADUC on L3_PWR: 17.14,22.99 15.49,22.99 15.37,22.86 15.37,18.92 17.27,17.02 17.27,16 17.65,15.62 19.43,15.62 19.69,15.37 19.69,8.89 19.94,8.64 26.03,8.64 26.03,16.64 25.78,16.89 23.62,16.89 23.24,17.27 23.24,19.18 22.99,19.43 17.91,19.43 17.27,20.07 17.27,22.86
DGND on TOP: 1.27,1.27 1.27,39.37 8.89,39.37 8.89,32.95 8.59,33.25 7.99,33.25 7.91,33.1 7.81,32.96 7.8,32.85 7.89,32.79 8.8,32.79 8.89,32.71 8.89,20.32 9.52,20.32 9.52,39.37 38.48,39.37 38.48,13.97 38.1,13.97 38.1,13.21 37.72,13.21 37.72,11.56 37.85,11.56 37.85,10.02 36.72,11.15 36.61,11.17 36.54,11.08 36.54,9.27 37.46,9.27 37.85,9.65 37.85,9.65 37.46,9.27 28.96,9.27 28.83,9.4 28.83,19.18 22.35,19.18 21.97,18.8 21.97,1.27 11.18,1.27 11.18,2.41 10.16,2.41 10.16,2.54 8.89,2.54 8.89,8.26 8.25,8.26 8.25,17.78 9.52,17.78 9.52,19.05 8.89,19.05 8.89,18.41 7.62,18.41 7.62,7.62 8.25,7.62 8.25,1.27 ; 21 cut-outs
DGND on BOTTOM: 8.89,25.91 9.52,25.91 9.52,39.37 38.48,39.37 38.48,10.29 37.46,9.27 28.96,9.27 28.83,9.4 28.83,19.18 22.35,19.18 21.97,18.8 21.97,1.27 8.89,1.27 8.89,7.62 8.25,7.62 8.25,1.27 1.27,1.27 1.27,39.37 8.89,39.37 ; 9 cut-outs
DGND on L2_GND: 1.27,1.27 1.27,39.37 8.89,39.37 8.89,20.32 9.52,20.32 9.52,39.37 38.48,39.37 38.48,10.29 37.46,9.27 28.96,9.27 28.83,9.4 28.83,19.18 22.35,19.18 21.97,18.8 21.97,1.27 8.89,1.27 8.89,8.26 8.25,8.26 8.25,17.78 9.52,17.78 9.52,19.05 8.89,19.05 8.89,18.41 7.62,18.41 7.62,7.62 8.25,7.62 8.25,1.27
FAULT on L3_PWR: 3.56,17.4 3.3,17.65 3.3,35.81 3.68,36.2 9.4,36.2 11.43,34.16 29.72,34.16 30.48,33.4 42.04,33.4 43.43,32 43.43,30.48 42.42,30.48 42.04,30.1 39.62,30.1 39.24,30.48 35.69,30.48 33.4,28.19 11.94,28.19 10.29,26.54 10.29,17.65 10.03,17.4
HART_CLK on L3_PWR: 10.03,8.51 10.03,14.86 10.41,15.24 14.1,15.24 14.48,14.86 14.48,3.68 14.6,3.56 36.58,3.56 40,6.98 51.94,6.98 52.07,6.86 52.07,1.27 43.82,1.27 13.21,1.27 1.27,1.27 1.27,8.51
IOVDD_ADUC on L3_PWR: 14.73,19.43 14.86,19.56 14.86,22.99 15.24,23.37 30.1,23.37 32,21.46 33.91,21.46 34.16,21.72 34.16,25.53 32.38,27.3 12.32,27.3 10.92,25.91 10.92,19.56 11.05,19.43
PMOD_CD on L3_PWR: 29.46,34.29 11.68,34.29 9.52,36.45 3.56,36.45 2.92,35.81 2.92,17.53 3.43,17.02 8.51,17.02 8.89,16.64 8.89,8.89 1.27,8.89 1.27,39.37 29.34,39.37 29.46,39.24

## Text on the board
BOTTOM: 08-037812 REV. A
Ref Des/Silkscreen Bottom: EVAL-CN0270-EB1Z REV A | VIN | GND | IOUT
Ref Des/Silkscreen Top: PMOD | 0 | XTAL | 1 | SPI PMOD | UART PMOD | JLINK
DIMENSION: (REF)
User.5: ROHS COMPLIANCE NOTE: | 100 MICRO INCHES NICKEL/ | 2-8 MICRO INCHES GOLD | THE EU RoHS DIRECTIVE 2002/95/EC | HOMOGENOUS MATERIALS IN THIS BOARD SHALL BE COMPLIANT
User.8: 08-      -01 | LAYER1 PRIMARY SIDE
User.9: 08-      -02 | LAYER2 SECONDARY SIDE
User.11: 08-      -07 | LAYER2_AGND
User.12: 08-      -08 | LAYER3_DGND
User.14: SECONDARY SIDE PASTEMASK | 08-      -12
User.17: 08-      -07 | L2 GND
User.18: 08-      -08 | L3 PWR
User.33: FIGURE | SIZE | 12.0 | 40.0 | 45.0 | 50.0 | DRILL CHART: TOP to BOTTOM | ALL UNITS ARE IN MILS | TOLERANCE | +3.0/-3.0 | PLATED | QTY | 190 | 14 | 41 | 4
